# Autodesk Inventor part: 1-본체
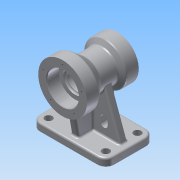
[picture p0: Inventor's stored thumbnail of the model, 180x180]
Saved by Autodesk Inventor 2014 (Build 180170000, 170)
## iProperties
Created: 2015-08
Part Number: 1-본체
Material: 알루미늄 6061
Document SubType Name: Modeling
Designer: study
Density: 2.71 g/cm^3
Appearance: 알루미늄 - 평지
Author: study
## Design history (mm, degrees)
sketch "스케치1"
  geometry: L1 (61, -40)-(-61, -40); L2 (-61, -40)-(-61, 40); L3 (-61, 40)-(61, 40); L4 (61, 40)-(61, -40); L5 (61, -40)-(-61, 40); L6 (-61, -40)-(61, 40); 1 further point
  constraints: 12 end point, 2 midpoint, 2 parallel, 1 horizontal, 1 perpendicular
  dimensions: "d0" = 122 distance of L2.end L3.end; "d1" = 80 distance of L1.end L2.end
extrude "돌출1" new body sketch "스케치1" distance "d2" = 12; taper "d3" = 0 deg
node "작업 평면1"
sketch "스케치2"
  geometry: L1 (-40, 90)-(50, 90); L2 (-40, 0)-(40, 0) reference; L3 (-40, 90)-(-40, 125); L4 (-40, 125)-(-20, 125); L5 (-20, 125)-(-14.804, 116); L6 (-14.804, 116)-(13.315, 116); L7 (13.315, 116)-(30, 130); L8 (30, 130)-(50, 130); L9 (50, 130)-(50, 90); 1 further point
  constraints: 16 end point, 3 parallel, 2 perpendicular, 1 horizontal, 1 vertical alignment
  dimensions: "d5" = 90 distance of L1.start L1.end; "d6" = 90 distance between parallel lines of L2 L1; "d7" = 70 diameter of L4 L1; "d8" = 80 diameter of L8 L1; "d9" = 52 diameter of L6 L1; "d10" = 60 deg angle of L6 L5; "d11" = 40 deg angle of L6 L7; "d12" = 20 distance of L3.end L4.end; "d13" = 20 distance of L7.end L8.end
revolve "회전1" sketch "스케치2" stored, may be unused: angle "d14" = 90 deg
node "작업 평면2"
sketch "스케치3"
  geometry: L1 (61, 12)-(-61, 12) reference; L2 (-51, 12)-(51, 12); L3 (51, 12)-(23.191, 88.404); L4 (-23.191, 88.404)-(23.191, 88.404); L5 (-23.191, 88.404)-(-51, 12); C1 r 35 at (0, 90) reference; 3 further points
  constraints: 8 end point, 2 collinear, 2 midpoint, 1 equal length, 1 parallel, 1 vertical alignment
  dimensions: "d17" = 10 distance of L1.end L2.start; "d20" = 70 deg angle of L1 L5; "d21" = 46.38258 distance of L4.start L3.end
extrude "돌출2" join sketch "스케치3" stored distance "d18" = 12; taper "d19" = 0 deg
sketch "스케치4"
  geometry: L1 (40, 12)-(-40, 12) reference; L2 (-30, 12)-(-30, 75.951); L3 (-30, 75.951)-(41.276, 75.951); L4 (41.276, 75.951)-(30, 12); L5 (-30, 12)-(30, 12); 1 further point
  constraints: 8 end point, 2 perpendicular, 2 point on line, 1 collinear
  dimensions: "d22" = 80 deg angle of L1 L4; "d23" = 10 distance of L2.start L1.end; "d24" = 10 distance of L1.start L4.end; "d25" = 71.27626 distance of L2.end L3.end
extrude "돌출3" join sketch "스케치4" stored distance "d26" = 12; taper "d27" = 0 deg
sketch "스케치5"
  geometry: L1 (47, -26)-(-47, -26); L2 (-47, -26)-(-47, 26); L3 (-47, 26)-(47, 26); L4 (47, 26)-(47, -26); L5 (47, -26)-(-47, 26); L6 (-47, -26)-(47, 26); 5 further points
  constraints: 12 end point, 4 coincident, 2 midpoint, 2 parallel, 1 horizontal, 1 perpendicular
  dimensions: "d28" = 94 distance of L2.end L3.end; "d29" = 52 distance of L1.end L2.end
hole "구멍1" sketch "스케치5" at (-47, 26), (-47, -26), (47, -26), (47, 26) diameter "d30" = 12; stored, may be unused: countersink angle "d34" = 90 deg, drill point angle "d36" = 118 deg; dims "d31" = 6, "d32" = 4, "d33" = 2, "d35" = 8
sketch "스케치6"
  geometry: L1 (-6, 12)-(-51, 12) reference; L2 (18, 36)-(18, 30); L3 (30, 30)-(30, 36); L4 (-30, 36)-(-30, 30); L5 (-18, 30)-(-18, 36); A1 r 6 centre (24, 30) between (18, 30) and (30, 30); A2 r 6 centre (24, 36) between (30, 36) and (18, 36); A3 r 6 centre (-24, 30) between (-30, 30) and (-18, 30); A4 r 6 centre (-24, 36) between (-18, 36) and (-30, 36); 1 further point
  constraints: 8 end point, 8 point on circle, 8 tangent, 4 centre point, 2 parallel, 1 horizontal alignment, 1 perpendicular, 1 vertical
  dimensions: "d37" = 18 distance from line of A1.centre L1; "d38" = 12 distance between parallel lines of L3 L2; "d39" = 18 dimension on A1 A2; "d40" = 12 distance between parallel lines of L5 L4; "d41" = 18 dimension on A3 A4; "d42" = 48 distance of A1.centre A3.centre; "d43" = 24 horizontal distance of A3.centre point (0, 0)
extrude "돌출4" cut sketch "스케치6" stored distance "d44" = 12; taper "d45" = 0 deg
hole "구멍2" diameter "d48" = 38; stored, may be unused: countersink angle "d52" = 90 deg, drill point angle "d54" = 0 deg; dims "d46" = 10, "d47" = 10, "d49" = 6, "d50" = 52, "d51" = 20, "d53" = 23
hole "구멍3" diameter "d57" = 32; stored, may be unused: countersink angle "d61" = 90 deg, drill point angle "d63" = 0 deg; dims "d55" = 10, "d56" = 10, "d58" = 6, "d59" = 40, "d60" = 17, "d62" = 23
sketch "스케치7" dims "d64" = 66
  geometry: C1 r 26 at (0, 0) reference; C2 r 40 at (0, 0) reference; 3 further points
  constraints: 2 vertical alignment, 1 coincident, 2 other
hole "구멍4" sketch "스케치7" at (0, 33) diameter "d65" = 3.242; stored, may be unused: countersink angle "d69" = 82 deg, drill point angle "d71" = 118 deg; dims "d66" = 10, "d67" = 3.023, "d68" = 17, "d70" = 13
sketch "스케치8" dims "d75" = 54
  geometry: C1 r 20 at (0, 0) reference; C2 r 35 at (0, 0) reference; 3 further points
  constraints: 2 vertical alignment, 1 coincident, 2 other
hole "구멍5" sketch "스케치8" at (0, -27) diameter "d76" = 3.242; stored, may be unused: countersink angle "d80" = 82 deg, drill point angle "d82" = 118 deg; dims "d77" = 10, "d78" = 3.023, "d79" = 17, "d81" = 13
chamfer "모따기1" distance "d86" = 1; stored, may be unused: second distance "d87" = 2, angle "d88" = 45 deg
fillet "모깎기1" dims "d89" = 0.3
fillet "모깎기2" dims "d90" = 3, "d91" = 14
fillet "모깎기3" dims "d92" = 3
sketch "스케치9"
  geometry: L1 (55.518, 30)-(12, 30) reference; L2 (12, 6)-(12, 30) reference; 2 further points
  constraints: 1 other
  dimensions: "d93" = 24 distance from line of point (36, 14) L2; "d94" = 16 distance from line of point (36, 14) L1
feature "엠보싱1" sketch "스케치9" dims "d0" = 122, "d1" = 80, "d95" = 0.5, "d96" = 0
fillet "모깎기4" dims "d97" = 3
fillet "모깎기5" dims "d98" = 3
fillet "모깎기6" dims "d99" = 3
node "솔리드1"
pattern_circular "원형 패턴1" dims angle "d73" = 360 deg
pattern_circular "원형 패턴2" dims angle "d84" = 360 deg
other parameters: "d4" = 0, "d15" = 0
